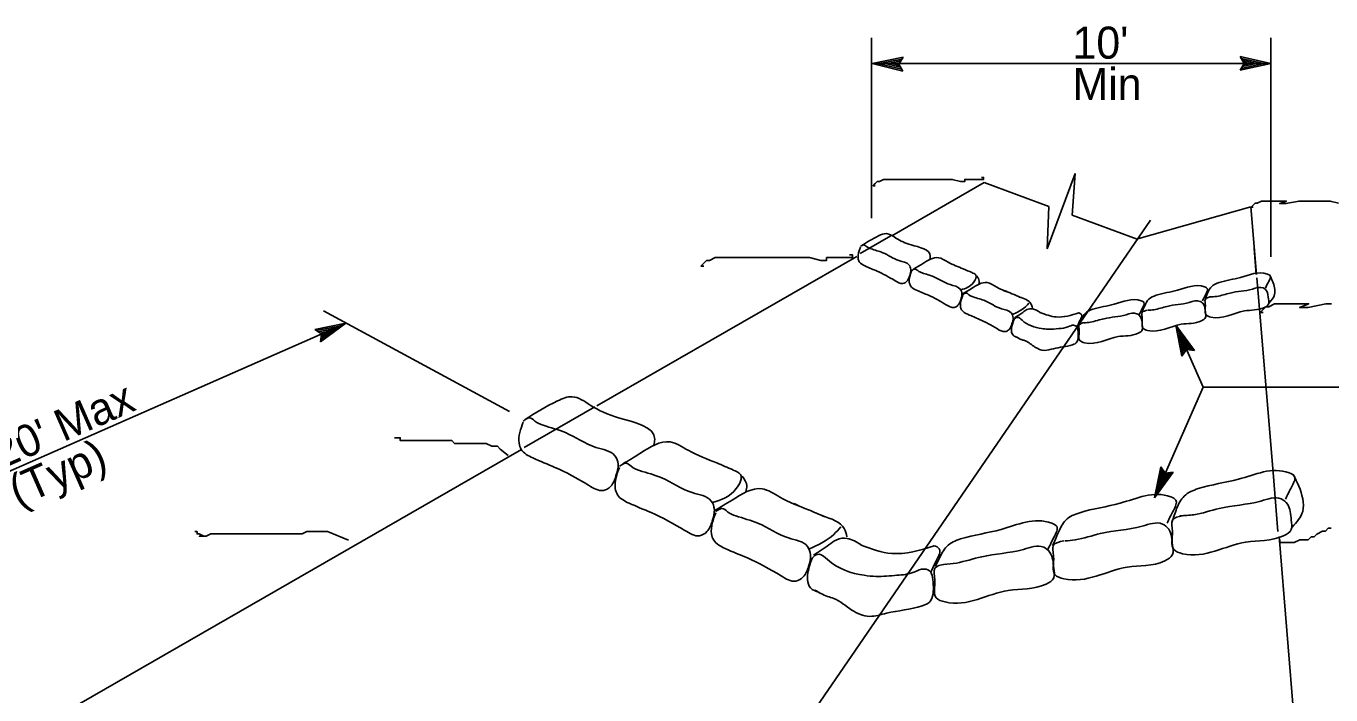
# Model space of a CAD drawing. Extents: x 6707415 to 6708768, y 1869893 to 1870831.
# Drawn here: x 6708364.3 to 6708608.7, y 1870292.4 to 1870417.6 of the extents above; entities that cross this region are included whole.
import ezdxf

# ---------------------------------------------------------------- set-up
doc = ezdxf.new("R2010")
doc.units = 0
for name, color, linetype in [('56 Stg 3 Anno', 7, 'Continuous'), ('57 Undefined', 7, 'Continuous'), ('60 Nongeo Data', 7, 'Continuous')]:
    doc.layers.add(name, color=color, linetype=linetype)

msp = doc.modelspace()

# ---------------------------------------------------------------- linework, layer by layer
at = {"layer": '56 Stg 3 Anno'}
for p, q in [((6708522.62, 1870415.42), (6708522.62, 1870381.62)), ((6708597.46, 1870415.42), (6708597.46, 1870374.39)), ((6708522.77, 1870410.59), (6708528.55, 1870411.75)), ((6708528.55, 1870411.75), (6708527.76, 1870410.49)), ((6708528.55, 1870411.75), (6708528.55, 1870411.75)), ((6708592.44, 1870410.62), (6708591.67, 1870411.91)), ((6708591.67, 1870411.91), (6708591.67, 1870411.91)), ((6708591.67, 1870411.91), (6708597.43, 1870410.62)), ((6708597.46, 1870410.62), (6708522.62, 1870410.62)), ((6708528.5, 1870409.19), (6708522.77, 1870410.59)), ((6708522.77, 1870410.59), (6708522.77, 1870410.59)), ((6708528.3, 1870409.54), (6708524.09, 1870410.56)), ((6708524.11, 1870410.57), (6708528.32, 1870411.41)), ((6708525.42, 1870410.54), (6708528.15, 1870411.08)), ((6708528.08, 1870409.89), (6708525.42, 1870410.54)), ((6708526.75, 1870410.51), (6708527.91, 1870410.74)), ((6708527.92, 1870410.22), (6708526.75, 1870410.51)), ((6708527.76, 1870410.49), (6708528.5, 1870409.19)), ((6708597.43, 1870410.62), (6708591.67, 1870409.34)), ((6708591.67, 1870409.34), (6708592.44, 1870410.62)), ((6708591.67, 1870409.34), (6708591.67, 1870409.34)), ((6708591.88, 1870411.56), (6708596.11, 1870410.62)), ((6708596.1, 1870410.62), (6708591.9, 1870409.69)), ((6708594.78, 1870410.62), (6708592.07, 1870410.02)), ((6708592.11, 1870411.22), (6708594.78, 1870410.62)), ((6708592.27, 1870410.89), (6708593.45, 1870410.62)), ((6708593.45, 1870410.62), (6708592.29, 1870410.37)), ((6708597.43, 1870410.62), (6708597.43, 1870410.62)), ((6708528.5, 1870409.19), (6708528.5, 1870409.19)), ((6708393.6, 1870117.38), (6708574.91, 1870381.27)), ((6708454.84, 1870345.44), (6708419.99, 1870364.28)), ((6708295.77, 1870305.59), (6708424.21, 1870362)), ((6708418.37, 1870360.83), (6708424.16, 1870361.98)), ((6708419.6, 1870359.97), (6708418.37, 1870360.83)), ((6708418.37, 1870360.83), (6708418.37, 1870360.83)), ((6708418.7, 1870360.6), (6708422.95, 1870361.45)), ((6708419.05, 1870360.38), (6708421.74, 1870360.91)), ((6708419.34, 1870360.14), (6708420.52, 1870360.38)), ((6708424.16, 1870361.98), (6708419.41, 1870358.49)), ((6708422.94, 1870361.44), (6708419.48, 1870358.89)), ((6708421.74, 1870360.91), (6708419.5, 1870359.27)), ((6708420.52, 1870360.38), (6708419.56, 1870359.67)), ((6708424.16, 1870361.98), (6708424.16, 1870361.98)), ((6708584.76, 1870350), (6708579.65, 1870361.61)), ((6708580.79, 1870355.82), (6708579.65, 1870361.61)), ((6708579.65, 1870361.61), (6708579.65, 1870361.61)), ((6708579.65, 1870361.61), (6708583.14, 1870356.86)), ((6708581.02, 1870356.15), (6708580.18, 1870360.4)), ((6708580.19, 1870360.39), (6708582.73, 1870356.92)), ((6708419.41, 1870358.49), (6708419.6, 1870359.97)), ((6708419.41, 1870358.49), (6708419.41, 1870358.49)), ((6708581.25, 1870356.5), (6708580.72, 1870359.18)), ((6708580.72, 1870359.18), (6708582.36, 1870356.95)), ((6708581.48, 1870356.78), (6708581.25, 1870357.97)), ((6708581.25, 1870357.97), (6708581.95, 1870357.01)), ((6708581.66, 1870357.04), (6708580.79, 1870355.82)), ((6708580.79, 1870355.82), (6708580.79, 1870355.82)), ((6708583.14, 1870356.86), (6708581.66, 1870357.04)), ((6708583.14, 1870356.86), (6708583.14, 1870356.86)), ((6708584.76, 1870350), (6708575.66, 1870329.32)), ((6708663.64, 1870350), (6708584.76, 1870350)), ((6708575.66, 1870329.32), (6708576.81, 1870335.11)), ((6708579.15, 1870334.08), (6708575.66, 1870329.32)), ((6708576.19, 1870330.55), (6708577.03, 1870334.77)), ((6708578.76, 1870334.03), (6708576.19, 1870330.54)), ((6708576.73, 1870331.75), (6708577.27, 1870334.48)), ((6708578.35, 1870333.96), (6708576.73, 1870331.75)), ((6708576.81, 1870335.11), (6708576.81, 1870335.11)), ((6708576.81, 1870335.11), (6708577.66, 1870333.89)), ((6708577.26, 1870332.97), (6708577.49, 1870334.13)), ((6708577.98, 1870333.94), (6708577.26, 1870332.97)), ((6708577.66, 1870333.89), (6708579.15, 1870334.08)), ((6708579.15, 1870334.08), (6708579.15, 1870334.08)), ((6708575.66, 1870329.32), (6708575.66, 1870329.32))]:
    msp.add_line(p, q, dxfattribs=at)
at = {"layer": '60 Nongeo Data'}
for p, q in [((6708555.57, 1870375.89), (6708560.78, 1870390.03)), ((6708560.78, 1870390.03), (6708560.22, 1870382.22)), ((6708526.45, 1870378.37), (6708543.72, 1870388.3)), ((6708555.57, 1870375.89), (6708555.88, 1870383.82)), ((6708572.29, 1870377.74), (6708593.69, 1870383.78)), ((6708594.74, 1870371.08), (6708593.69, 1870383.78)), ((6708520.5, 1870375.03), (6708526.29, 1870378.36)), ((6708594.71, 1870371.11), (6708594.31, 1870375.97)), ((6708471.2, 1870346.5), (6708519.88, 1870374.48)), ((6708595.31, 1870364.62), (6708594.82, 1870370.48)), ((6708547.54, 1870368.12), (6708547.98, 1870367.91)), ((6708597.85, 1870334.03), (6708595.31, 1870364.62)), ((6708457.58, 1870338.73), (6708470.84, 1870346.35)), ((6708364.4, 1870285.1), (6708457.05, 1870338.34)), ((6708598.76, 1870323), (6708597.85, 1870334.03)), ((6708508.18, 1870328.22), (6708509.01, 1870327.83)), ((6708603.97, 1870261.83), (6708598.97, 1870322.05))]:
    msp.add_line(p, q, dxfattribs=at)
for points in [[(6708523.33, 1870387.72), (6708522.94, 1870387.72), (6708523.33, 1870388.11), (6708523.72, 1870388.5), (6708524.11, 1870388.5), (6708524.89, 1870388.89), (6708525.67, 1870388.89), (6708526.06, 1870388.89), (6708526.84, 1870388.89), (6708527.62, 1870388.89), (6708528.01, 1870388.89), (6708528.4, 1870388.89), (6708529.18, 1870388.89), (6708529.57, 1870388.89), (6708529.96, 1870388.89), (6708531.13, 1870388.89), (6708531.91, 1870388.89), (6708532.3, 1870388.89), (6708532.69, 1870388.89), (6708533.08, 1870388.89), (6708533.47, 1870388.89), (6708533.86, 1870388.89), (6708534.25, 1870388.89), (6708534.64, 1870388.89), (6708535.03, 1870388.89), (6708535.81, 1870388.89), (6708536.59, 1870388.89), (6708537.37, 1870388.89), (6708537.77, 1870388.89), (6708539.33, 1870388.5), (6708540.11, 1870388.5), (6708540.11, 1870388.89), (6708540.89, 1870388.89), (6708541.28, 1870388.89), (6708541.67, 1870388.89), (6708542.06, 1870388.89), (6708542.45, 1870388.89), (6708542.84, 1870388.89), (6708543.23, 1870388.89), (6708543.23, 1870388.89), (6708543.62, 1870388.89), (6708543.62, 1870389.28), (6708543.23, 1870389.28)], [(6708555.88, 1870383.82), (6708543.72, 1870388.3)], [(6708594.13, 1870383.69), (6708593.74, 1870383.69), (6708594.13, 1870384.08), (6708594.52, 1870384.47), (6708594.91, 1870384.47), (6708595.69, 1870384.85), (6708596.47, 1870384.86), (6708596.86, 1870384.86), (6708597.64, 1870384.86), (6708598.42, 1870384.85), (6708598.81, 1870384.86), (6708599.2, 1870384.85), (6708599.98, 1870384.86), (6708600.37, 1870384.85), (6708599.11, 1870384.37), (6708600.28, 1870384.37), (6708602.72, 1870384.86), (6708603.11, 1870384.85), (6708603.5, 1870384.86), (6708603.89, 1870384.86), (6708604.28, 1870384.86), (6708604.67, 1870384.86), (6708605.06, 1870384.86), (6708605.45, 1870384.86), (6708605.84, 1870384.86), (6708606.62, 1870384.86), (6708607.4, 1870384.86), (6708608.18, 1870384.86), (6708608.57, 1870384.85), (6708610.13, 1870384.47)], [(6708572.38, 1870377.74), (6708560.22, 1870382.22)], [(6708491.23, 1870372.68), (6708490.69, 1870372.68), (6708491.23, 1870373.21), (6708491.76, 1870373.74), (6708492.3, 1870373.74), (6708493.37, 1870374.28), (6708494.44, 1870374.28), (6708494.98, 1870374.28), (6708496.05, 1870374.28), (6708497.12, 1870374.28), (6708497.65, 1870374.28), (6708498.19, 1870374.28), (6708499.26, 1870374.28), (6708499.79, 1870374.28), (6708500.33, 1870374.28), (6708501.93, 1870374.28), (6708503, 1870374.28), (6708503.54, 1870374.28), (6708504.07, 1870374.28), (6708504.61, 1870374.28), (6708505.15, 1870374.28), (6708505.68, 1870374.28), (6708506.22, 1870374.28), (6708506.75, 1870374.28), (6708507.29, 1870374.28), (6708508.36, 1870374.28), (6708509.43, 1870374.28), (6708510.5, 1870374.28), (6708511.03, 1870374.28), (6708513.17, 1870373.74), (6708514.24, 1870373.74), (6708514.24, 1870374.28), (6708515.32, 1870374.28), (6708515.85, 1870374.28), (6708516.39, 1870374.28), (6708516.92, 1870374.28), (6708517.46, 1870374.28), (6708517.99, 1870374.28), (6708518.53, 1870374.28), (6708518.53, 1870374.28), (6708519.06, 1870374.28), (6708519.06, 1870374.81), (6708518.53, 1870374.81)], [(6708595.98, 1870364.01), (6708595.45, 1870364.01), (6708595.98, 1870364.55), (6708596.52, 1870365.08), (6708597.05, 1870365.08), (6708598.12, 1870365.62), (6708599.19, 1870365.62), (6708599.73, 1870365.62), (6708600.8, 1870365.62), (6708601.87, 1870365.62), (6708602.41, 1870365.62), (6708602.94, 1870365.62), (6708604.01, 1870365.62), (6708604.55, 1870365.62), (6708602.81, 1870364.95), (6708604.41, 1870364.95), (6708607.76, 1870365.62), (6708608.29, 1870365.62), (6708608.83, 1870365.62)], [(6708454.56, 1870337.2), (6708453.11, 1870338.42), (6708452.58, 1870338.96), (6708452.04, 1870338.96), (6708451.51, 1870338.96), (6708450.44, 1870339.49), (6708449.9, 1870339.49), (6708449.37, 1870339.49), (6708448.83, 1870339.49), (6708448.3, 1870339.49), (6708447.76, 1870339.49), (6708447.23, 1870339.49), (6708446.69, 1870339.49), (6708446.15, 1870339.49), (6708445.62, 1870339.49), (6708445.08, 1870339.49), (6708444.55, 1870339.49), (6708444.01, 1870340.02), (6708442.94, 1870340.02), (6708442.41, 1870340.02), (6708441.87, 1870340.02), (6708441.34, 1870340.02), (6708440.27, 1870340.02), (6708439.2, 1870340.02), (6708438.66, 1870340.02), (6708438.13, 1870340.02), (6708437.06, 1870340.02), (6708436.52, 1870340.02), (6708435.98, 1870340.02), (6708435.45, 1870340.02), (6708434.91, 1870340.02), (6708434.38, 1870340.02), (6708434.38, 1870340.02), (6708434.38, 1870340.56), (6708433.84, 1870340.56), (6708433.31, 1870340.56)], [(6708424.65, 1870321.36), (6708420.71, 1870322.98), (6708420.28, 1870322.98), (6708419.43, 1870322.98), (6708419, 1870322.98), (6708418.14, 1870322.98), (6708416.86, 1870322.98), (6708416, 1870322.55), (6708414.72, 1870322.55), (6708413, 1870322.55), (6708412.15, 1870322.55), (6708410.86, 1870322.55), (6708410.43, 1870322.55), (6708409.58, 1870322.55), (6708408.72, 1870322.55), (6708407.44, 1870322.55), (6708406.58, 1870322.55), (6708405.3, 1870322.55), (6708404.44, 1870322.55), (6708403.15, 1870322.55), (6708401.87, 1870322.55), (6708400.59, 1870322.55), (6708399.73, 1870322.55), (6708398.87, 1870322.55), (6708398.02, 1870322.12), (6708397.59, 1870322.12), (6708396.73, 1870322.12), (6708397.59, 1870322.12), (6708396.73, 1870322.55), (6708396.3, 1870322.55), (6708396.3, 1870322.98), (6708395.88, 1870322.98)], [(6708599.11, 1870321.47), (6708599.11, 1870320.93), (6708599.64, 1870320.93), (6708600.71, 1870320.93), (6708601.78, 1870320.93), (6708602.85, 1870321.47), (6708603.39, 1870321.47), (6708603.92, 1870321.47), (6708604.46, 1870321.47), (6708605, 1870322), (6708605.53, 1870322), (6708606.07, 1870322.53), (6708607.14, 1870323.07), (6708607.67, 1870323.07), (6708608.21, 1870323.6), (6708608.74, 1870323.6)]]:
    msp.add_lwpolyline(points, dxfattribs=at)
for points in [[(6708520.73, 1870376.49), (6708523.97, 1870378.33), (6708525.44, 1870378.75), (6708527.22, 1870377.91), (6708530.05, 1870376.66), (6708533.64, 1870374.51), (6708533.55, 1870373.95)], [(6708520.56, 1870376.22), (6708520.14, 1870374.13), (6708520.35, 1870373.5), (6708521.5, 1870372.67), (6708523.7, 1870371.72), (6708527.06, 1870369.94), (6708528.53, 1870369.42), (6708529.26, 1870369.84), (6708529.79, 1870370.89), (6708530, 1870372.04), (6708529.68, 1870372.88), (6708527.79, 1870373.71), (6708524.75, 1870375.18), (6708522.55, 1870375.91), (6708521.71, 1870376.33), (6708521.19, 1870376.64), (6708520.87, 1870376.54), (6708520.56, 1870376.33)], [(6708530.46, 1870372.07), (6708532.21, 1870373.13), (6708535.19, 1870374.25), (6708536.98, 1870373.42), (6708539.81, 1870372.16), (6708541.44, 1870371.47)], [(6708530.14, 1870371.72), (6708529.72, 1870369.63), (6708529.93, 1870369), (6708531.08, 1870368.16), (6708533.29, 1870367.22), (6708536.64, 1870365.44), (6708538.11, 1870364.92), (6708538.84, 1870365.34), (6708539.37, 1870366.39), (6708539.58, 1870367.54), (6708539.26, 1870368.37), (6708537.38, 1870369.21), (6708534.33, 1870370.68), (6708532.13, 1870371.41), (6708531.29, 1870371.83), (6708530.77, 1870372.14), (6708530.45, 1870372.04), (6708530.14, 1870371.83)], [(6708539.39, 1870368.23), (6708541.76, 1870369.61), (6708542.17, 1870371.02), (6708541.41, 1870371.46)], [(6708542.36, 1870370.85), (6708542.8, 1870369.88), (6708542.72, 1870369.33)], [(6708596.43, 1870368.56), (6708597.05, 1870369.81), (6708597.31, 1870370.86), (6708596.8, 1870371.17), (6708591.77, 1870370.55), (6708587.74, 1870369.6), (6708586.36, 1870368.87), (6708585.6, 1870367.61), (6708585.14, 1870366.27)], [(6708597.2, 1870371.01), (6708598.15, 1870368.6), (6708598.15, 1870367.35), (6708597.1, 1870365.78)], [(6708539.58, 1870367.4), (6708541.34, 1870368.46), (6708544.32, 1870369.59), (6708546.1, 1870368.75), (6708548.94, 1870367.5), (6708550.56, 1870366.81)], [(6708584.64, 1870366.17), (6708585.27, 1870367.42), (6708585.52, 1870368.47), (6708585.02, 1870368.78), (6708579.98, 1870368.16), (6708575.96, 1870367.21), (6708574.57, 1870366.48), (6708573.82, 1870365.23), (6708573.26, 1870363.95)], [(6708586.18, 1870366.9), (6708585.18, 1870366.49), (6708585.18, 1870365.33), (6708585.3, 1870363.56), (6708586.18, 1870363.14), (6708592.48, 1870364.29), (6708596.25, 1870364.92), (6708597.01, 1870365.54), (6708597.01, 1870366.49), (6708596.63, 1870368.06), (6708596, 1870368.58), (6708593.99, 1870368.37), (6708589.83, 1870367.64), (6708587.32, 1870367.01), (6708585.93, 1870366.9)], [(6708539.72, 1870367.21), (6708539.3, 1870365.12), (6708539.51, 1870364.49), (6708540.66, 1870363.65), (6708542.87, 1870362.71), (6708546.22, 1870360.93), (6708547.69, 1870360.41), (6708548.43, 1870360.83), (6708548.95, 1870361.87), (6708549.16, 1870363.02), (6708548.85, 1870363.86), (6708546.96, 1870364.7), (6708543.92, 1870366.16), (6708541.71, 1870366.9), (6708540.87, 1870367.31), (6708540.35, 1870367.63), (6708540.04, 1870367.52), (6708539.72, 1870367.31)], [(6708548.95, 1870363.58), (6708551.47, 1870365.05), (6708552.17, 1870365.82)], [(6708550.31, 1870366.89), (6708552.5, 1870365.63), (6708552.77, 1870364.82)], [(6708572.78, 1870363.55), (6708573.41, 1870364.81), (6708573.66, 1870365.86), (6708573.16, 1870366.17), (6708568.12, 1870365.54), (6708564.09, 1870364.6), (6708562.71, 1870363.87), (6708561.95, 1870362.61), (6708561.58, 1870361.88)], [(6708574.36, 1870364.41), (6708573.36, 1870363.99), (6708573.36, 1870362.84), (6708573.48, 1870361.06), (6708574.36, 1870360.64), (6708580.66, 1870361.79), (6708584.43, 1870362.42), (6708585.19, 1870363.05), (6708585.19, 1870363.99), (6708584.81, 1870365.56), (6708584.18, 1870366.08), (6708582.17, 1870365.88), (6708578.01, 1870365.14), (6708575.5, 1870364.51), (6708574.47, 1870364.41)], [(6708550, 1870359.31), (6708549.16, 1870359.73), (6708548.84, 1870360.57), (6708549.16, 1870362.24), (6708549.47, 1870362.87), (6708550, 1870363.08), (6708550.84, 1870362.55), (6708554.51, 1870360.98), (6708555.66, 1870360.88), (6708557.76, 1870360.98), (6708559.44, 1870361.3), (6708560.49, 1870361.61), (6708561.12, 1870361.3), (6708561.32, 1870360.57), (6708561.22, 1870358.68), (6708561.12, 1870358.47), (6708560.28, 1870357.95), (6708556.71, 1870357.22), (6708555.03, 1870356.9), (6708553.25, 1870357.53), (6708551.47, 1870358.68), (6708550.84, 1870358.89), (6708549.58, 1870359.52)], [(6708554.21, 1870364.01), (6708552.79, 1870364.66), (6708551.76, 1870364.53), (6708550.98, 1870364.01), (6708549.43, 1870362.98)], [(6708554.19, 1870363.99), (6708557.24, 1870363.16), (6708561.45, 1870363.91)], [(6708561.13, 1870361.29), (6708561.73, 1870362.56), (6708561.96, 1870363.61), (6708561.45, 1870363.91), (6708561.4, 1870363.91)], [(6708562.54, 1870362.1), (6708561.54, 1870361.68), (6708561.54, 1870360.53), (6708561.66, 1870358.75), (6708562.54, 1870358.33), (6708568.84, 1870359.48), (6708572.61, 1870360.11), (6708573.37, 1870360.74), (6708573.37, 1870361.68), (6708572.99, 1870363.25), (6708572.36, 1870363.77), (6708570.35, 1870363.57), (6708566.19, 1870362.83), (6708563.68, 1870362.2), (6708562.41, 1870362.04)], [(6708457.74, 1870343.97), (6708463.83, 1870347.44), (6708466.59, 1870348.23), (6708469.95, 1870346.66), (6708475.28, 1870344.29), (6708482.03, 1870340.24), (6708481.86, 1870339.2)], [(6708457.41, 1870343.48), (6708456.62, 1870339.54), (6708457.02, 1870338.36), (6708459.19, 1870336.78), (6708463.33, 1870335.01), (6708469.65, 1870331.66), (6708472.41, 1870330.68), (6708473.79, 1870331.46), (6708474.78, 1870333.43), (6708475.17, 1870335.6), (6708474.58, 1870337.18), (6708471.03, 1870338.75), (6708465.31, 1870341.51), (6708461.16, 1870342.89), (6708459.58, 1870343.68), (6708458.59, 1870344.27), (6708458, 1870344.07), (6708457.41, 1870343.68)], [(6708476.04, 1870335.65), (6708479.34, 1870337.65), (6708484.95, 1870339.77), (6708488.31, 1870338.2), (6708493.64, 1870335.83), (6708496.7, 1870334.54)], [(6708475.44, 1870335.01), (6708474.65, 1870331.07), (6708475.05, 1870329.89), (6708477.22, 1870328.31), (6708481.36, 1870326.54), (6708487.68, 1870323.19), (6708490.44, 1870322.21), (6708491.82, 1870322.99), (6708492.81, 1870324.96), (6708493.2, 1870327.13), (6708492.61, 1870328.71), (6708489.06, 1870330.28), (6708483.34, 1870333.04), (6708479.19, 1870334.42), (6708477.61, 1870335.21), (6708476.63, 1870335.8), (6708476.03, 1870335.6), (6708475.44, 1870335.21)], [(6708492.85, 1870328.43), (6708497.32, 1870331.03), (6708498.09, 1870333.68), (6708496.66, 1870334.5)], [(6708600.17, 1870329.05), (6708601.36, 1870331.41), (6708601.83, 1870333.38), (6708600.88, 1870333.97), (6708591.41, 1870332.79), (6708583.83, 1870331.02), (6708581.23, 1870329.64), (6708579.8, 1870327.28), (6708578.94, 1870324.75)], [(6708601.63, 1870333.67), (6708603.41, 1870329.13), (6708603.41, 1870326.77), (6708601.43, 1870323.82)], [(6708493.21, 1870326.88), (6708496.52, 1870328.88), (6708502.13, 1870331), (6708505.48, 1870329.42), (6708510.81, 1870327.06), (6708513.88, 1870325.76)], [(6708498.44, 1870333.36), (6708499.28, 1870331.54), (6708499.11, 1870330.5)], [(6708578, 1870324.55), (6708579.18, 1870326.92), (6708579.65, 1870328.89), (6708578.71, 1870329.48), (6708569.23, 1870328.3), (6708561.66, 1870326.52), (6708559.05, 1870325.14), (6708557.63, 1870322.78), (6708556.57, 1870320.38)], [(6708580.9, 1870325.94), (6708579, 1870325.15), (6708579, 1870322.99), (6708579.24, 1870319.64), (6708580.9, 1870318.85), (6708592.74, 1870321.02), (6708599.84, 1870322.2), (6708601.27, 1870323.38), (6708601.27, 1870325.15), (6708600.56, 1870328.11), (6708599.37, 1870329.09), (6708595.58, 1870328.7), (6708587.77, 1870327.32), (6708583.03, 1870326.14), (6708580.42, 1870325.94)], [(6708493.47, 1870326.52), (6708492.68, 1870322.58), (6708493.08, 1870321.4), (6708495.25, 1870319.82), (6708499.39, 1870318.05), (6708505.71, 1870314.7), (6708508.47, 1870313.71), (6708509.85, 1870314.5), (6708510.84, 1870316.47), (6708511.23, 1870318.64), (6708510.64, 1870320.21), (6708507.09, 1870321.79), (6708501.37, 1870324.55), (6708497.22, 1870325.93), (6708495.64, 1870326.71), (6708494.66, 1870327.3), (6708494.06, 1870327.11), (6708493.47, 1870326.71)], [(6708510.84, 1870319.69), (6708515.58, 1870322.45), (6708516.89, 1870323.9)], [(6708513.4, 1870325.92), (6708517.52, 1870323.54), (6708518.03, 1870322.01)], [(6708555.67, 1870319.63), (6708556.86, 1870322), (6708557.33, 1870323.97), (6708556.39, 1870324.56), (6708546.91, 1870323.38), (6708539.33, 1870321.6), (6708536.73, 1870320.22), (6708535.31, 1870317.86), (6708534.6, 1870316.48)], [(6708558.66, 1870321.25), (6708556.76, 1870320.46), (6708556.76, 1870318.29), (6708557, 1870314.94), (6708558.66, 1870314.16), (6708570.5, 1870316.32), (6708577.6, 1870317.5), (6708579.02, 1870318.69), (6708579.02, 1870320.46), (6708578.31, 1870323.41), (6708577.13, 1870324.4), (6708573.34, 1870324), (6708565.53, 1870322.63), (6708560.79, 1870321.44), (6708558.86, 1870321.25)], [(6708520.73, 1870320.5), (6708518.06, 1870321.71), (6708516.12, 1870321.47), (6708514.66, 1870320.5), (6708511.75, 1870318.56)], [(6708520.7, 1870320.46), (6708526.43, 1870318.89), (6708534.35, 1870320.31)], [(6708533.75, 1870315.37), (6708534.89, 1870317.76), (6708535.32, 1870319.74), (6708534.36, 1870320.31), (6708534.27, 1870320.31)], [(6708536.41, 1870316.9), (6708534.52, 1870316.11), (6708534.52, 1870313.95), (6708534.76, 1870310.6), (6708536.41, 1870309.81), (6708548.26, 1870311.98), (6708555.36, 1870313.16), (6708556.78, 1870314.34), (6708556.78, 1870316.11), (6708556.07, 1870319.07), (6708554.89, 1870320.05), (6708551.1, 1870319.66), (6708543.28, 1870318.28), (6708538.55, 1870317.1), (6708536.16, 1870316.8)], [(6708512.81, 1870311.65), (6708511.23, 1870312.44), (6708510.64, 1870314.01), (6708511.23, 1870317.17), (6708511.82, 1870318.35), (6708512.81, 1870318.74), (6708514.39, 1870317.76), (6708521.29, 1870314.8), (6708523.47, 1870314.6), (6708527.41, 1870314.8), (6708530.57, 1870315.39), (6708532.54, 1870315.98), (6708533.73, 1870315.39), (6708534.12, 1870314.01), (6708533.93, 1870310.47), (6708533.73, 1870310.07), (6708532.15, 1870309.09), (6708525.44, 1870307.71), (6708522.28, 1870307.12), (6708518.93, 1870308.3), (6708515.57, 1870310.47), (6708514.39, 1870310.86), (6708512.02, 1870312.04)]]:
    msp.add_spline(points, degree=3, dxfattribs=at)

# ---------------------------------------------------------------- texts
at = {"layer": '57 Undefined'}
for s, p in [("10'", (6708560.3, 1870411.5)), ('Min', (6708560.3, 1870403.74))]:
    msp.add_text(s, height=6, dxfattribs=at).set_placement(p)
for s, p in [("20' Max", (6708359.66, 1870334.62)), ('(Typ)', (6708362.78, 1870327.51))]:
    msp.add_text(s, height=6, rotation=23.7096, dxfattribs=at).set_placement(p)

doc.saveas('drawing.dxf')
